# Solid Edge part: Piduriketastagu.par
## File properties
Author: Türk
Template: Iso Part.par
Last saved by: Türk
Revision: 14
Application: Solid Edge
Accuracy: 0,990
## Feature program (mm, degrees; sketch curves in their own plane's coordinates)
pattern "PatternOccurrence_1"  XOffset = 72 deg
pattern "PatternOccurrence_4"  XOffset = 21.1765 deg
pattern "PatternOccurrence_5"  XCount = 17; XOffset = 21.1765 deg
pattern "PatternOccurrence_3"  XCount = 17; XOffset = 21.1765 deg
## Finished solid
Body 1: sheet body, 1 face, 36 edges, 36 vertices.
  Faces by surface: plane 1
  Edges by curve: line 36
Body 2: solid body, 367 faces, 930 edges, 578 vertices.
  Faces by surface: plane 206, swept 68, cone 35, spline 34, cylinder 24
  Edges by curve: line 374, circle 250, spline 170, intersection 102, curve on surface 34
Bounding box of the edges (mm; curved faces can reach further): 260.000 x 30.000 x 260.000, from (-130, -15, -130) to (130, 15, 130).
Cylindrical faces by radius (mm): R6 x5, R62.1667 x17, R62.5 x1, R130 x1
Conical faces (half-angle, radius in mm at the cone's reference point): 18.4349 deg R57.5 x1, 45 deg R129 x17, 45 deg R130 x17
Planar faces by outward normal: +y 52, -y 69, oblique 85
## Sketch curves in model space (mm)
arc centre (0, -15, 0) radius 62.6082 from (7.4909, -15, 62.1584) through (9.4393, -15, 61.8925) to (11.3785, -15, 61.5655)
spline (-21.5657, 5, -127.1846) -> (-7.0582, 5, -96.3807) -> (3.4351, 5, -64.8637)
spline (0.1279, 5, -62.6081) -> (-10.6081, 5, -94.9886) -> (-25.2727, 5, -126.5002)
line (62.5, 0, 20) -> (62.5, 0, 0)
line (62.5, 0, 0) -> (62.5, -10, 0)
line (62.5, -10, 0) -> (62.5, -10, 20)
line (62.5, -10, 20) -> (62.5, 0, 20)
line (130, -15, 0) -> (130, 5, 0)
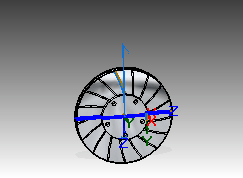
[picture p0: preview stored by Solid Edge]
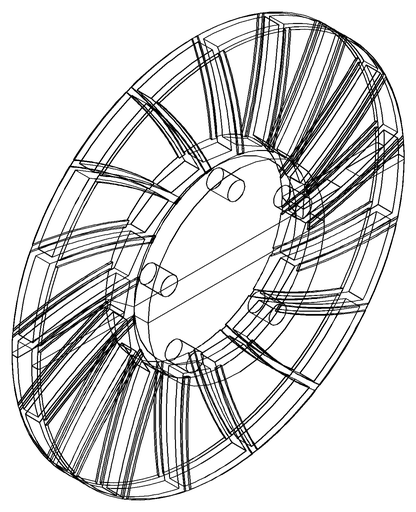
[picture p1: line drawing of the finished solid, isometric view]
